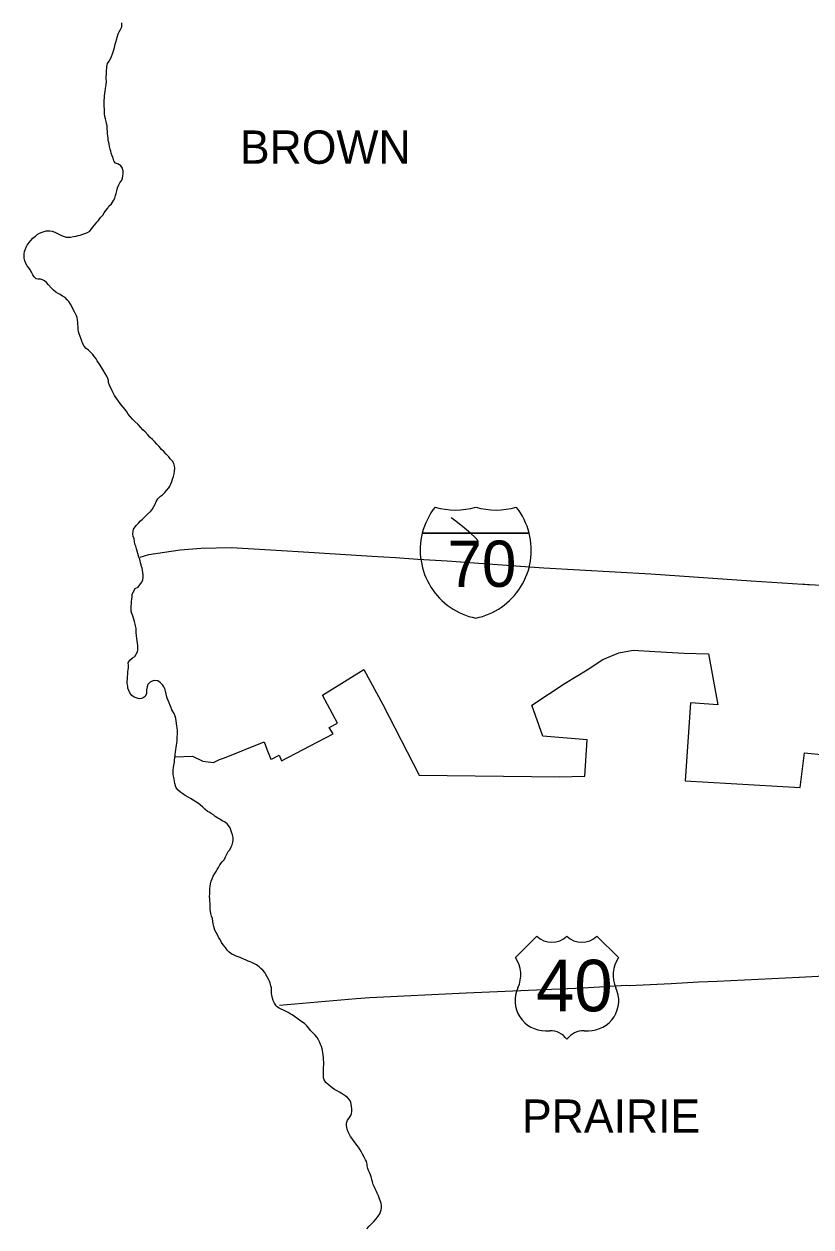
# Model space of a CAD drawing. Extents: x -1146 to -445, y -1283 to -822.
# Drawn here: x -1066.7 to -1013.6, y -1085.1 to -1003.9 of the extents above; entities that cross this region are included whole.
import ezdxf

# ---------------------------------------------------------------- set-up
doc = ezdxf.new("R2010")
doc.units = 0
for name, color, linetype in [('GM_X_County', 7, 'Continuous'), ('GM_X_County_Road', 7, 'Continuous'), ('GM_X_Interstate_Route', 7, 'Continuous'), ('GM_X_Interstate_Shield', 7, 'Continuous'), ('GM_X_Township', 7, 'Continuous'), ('GM_X_Township_Text', 7, 'Continuous'), ('GM_X_US_Route', 7, 'Continuous'), ('GM_X_US_Shield', 7, 'Continuous')]:
    doc.layers.add(name, color=color, linetype=linetype)

msp = doc.modelspace()

# ---------------------------------------------------------------- linework, layer by layer
at = {"layer": 'GM_X_County'}
msp.add_lwpolyline([(-1043.557, -1085.277), (-1043.4, -1085.092), (-1043.259, -1084.932), (-1043.097, -1084.782), (-1042.935, -1084.602), (-1042.793, -1084.422), (-1042.686, -1084.262), (-1042.64, -1084.137), (-1042.599, -1083.996), (-1042.583, -1083.826), (-1042.572, -1083.695), (-1042.592, -1083.564), (-1042.636, -1083.429), (-1042.72, -1083.257), (-1042.784, -1083.051), (-1042.869, -1082.875), (-1042.908, -1082.749), (-1042.993, -1082.583), (-1043.067, -1082.422), (-1043.137, -1082.281), (-1043.191, -1082.095), (-1043.225, -1081.944), (-1043.274, -1081.773), (-1043.329, -1081.637), (-1043.383, -1081.481), (-1043.452, -1081.325), (-1043.492, -1081.2), (-1043.541, -1081.029), (-1043.55, -1080.903), (-1043.595, -1080.737), (-1043.664, -1080.606), (-1043.754, -1080.435), (-1043.863, -1080.234), (-1043.932, -1080.098), (-1044.007, -1079.947), (-1044.137, -1079.765), (-1044.231, -1079.624), (-1044.331, -1079.498), (-1044.486, -1079.292), (-1044.58, -1079.16), (-1044.665, -1079.029), (-1044.745, -1078.904), (-1044.829, -1078.727), (-1044.893, -1078.551), (-1044.922, -1078.416), (-1044.942, -1078.29), (-1044.931, -1078.134), (-1044.864, -1077.944), (-1044.773, -1077.814), (-1044.656, -1077.613), (-1044.605, -1077.483), (-1044.584, -1077.357), (-1044.573, -1077.167), (-1044.592, -1077.016), (-1044.621, -1076.865), (-1044.656, -1076.739), (-1044.725, -1076.578), (-1044.875, -1076.412), (-1045.035, -1076.301), (-1045.295, -1076.119), (-1045.421, -1076.053), (-1045.581, -1075.967), (-1045.746, -1075.865), (-1045.916, -1075.749), (-1046.051, -1075.643), (-1046.177, -1075.537), (-1046.331, -1075.385), (-1046.446, -1075.219), (-1046.485, -1075.068), (-1046.504, -1074.912), (-1046.503, -1074.747), (-1046.497, -1074.581), (-1046.486, -1074.375), (-1046.48, -1074.194), (-1046.474, -1074.019), (-1046.483, -1073.848), (-1046.497, -1073.717), (-1046.511, -1073.531), (-1046.53, -1073.371), (-1046.589, -1073.109), (-1046.638, -1072.953), (-1046.688, -1072.817), (-1046.772, -1072.641), (-1046.831, -1072.515), (-1046.931, -1072.349), (-1047.061, -1072.203), (-1047.191, -1072.052), (-1047.36, -1071.885), (-1047.485, -1071.714), (-1047.62, -1071.563), (-1047.78, -1071.416), (-1047.945, -1071.3), (-1048.11, -1071.189), (-1048.29, -1071.057), (-1048.606, -1070.83), (-1048.736, -1070.759), (-1048.886, -1070.663), (-1049.057, -1070.571), (-1049.192, -1070.505), (-1049.362, -1070.439), (-1049.488, -1070.383), (-1049.663, -1070.257), (-1049.721, -1070.168), (-1049.802, -1070.041), (-1049.887, -1069.864), (-1049.941, -1069.693), (-1049.985, -1069.497), (-1049.999, -1069.367), (-1050.003, -1069.206), (-1050.012, -1069.005), (-1050.042, -1068.874), (-1050.096, -1068.693), (-1050.145, -1068.548), (-1050.21, -1068.422), (-1050.299, -1068.261), (-1050.394, -1068.095), (-1050.458, -1067.969), (-1050.588, -1067.802), (-1050.718, -1067.701), (-1050.848, -1067.59), (-1051.023, -1067.459), (-1051.199, -1067.363), (-1051.324, -1067.297), (-1051.449, -1067.236), (-1051.575, -1067.19), (-1051.705, -1067.129), (-1051.871, -1067.073), (-1051.996, -1067.022), (-1052.126, -1066.962), (-1052.262, -1066.911), (-1052.397, -1066.855), (-1052.522, -1066.799), (-1052.683, -1066.733), (-1052.858, -1066.597), (-1053.003, -1066.45), (-1053.118, -1066.284), (-1053.267, -1066.108), (-1053.392, -1065.931), (-1053.481, -1065.745), (-1053.556, -1065.614), (-1053.63, -1065.468), (-1053.75, -1065.272), (-1053.834, -1065.106), (-1053.898, -1064.865), (-1053.937, -1064.689), (-1053.961, -1064.513), (-1053.995, -1064.327), (-1054.05, -1064.156), (-1054.099, -1063.985), (-1054.128, -1063.829), (-1054.143, -1063.704), (-1054.151, -1063.433), (-1054.155, -1063.292), (-1054.159, -1063.156), (-1054.173, -1062.991), (-1054.183, -1062.835), (-1054.176, -1062.664), (-1054.175, -1062.499), (-1054.164, -1062.313), (-1054.153, -1062.132), (-1054.127, -1061.987), (-1054.071, -1061.807), (-1054.019, -1061.631), (-1053.933, -1061.461), (-1053.831, -1061.281), (-1053.745, -1061.146), (-1053.674, -1061.015), (-1053.588, -1060.875), (-1053.486, -1060.695), (-1053.334, -1060.5), (-1053.207, -1060.35), (-1053.121, -1060.15), (-1053.024, -1059.979), (-1052.928, -1059.804), (-1052.826, -1059.674), (-1052.73, -1059.484), (-1052.663, -1059.334), (-1052.607, -1059.158), (-1052.596, -1059.003), (-1052.6, -1058.847), (-1052.634, -1058.666), (-1052.699, -1058.495), (-1052.748, -1058.334), (-1052.801, -1058.189), (-1052.904, -1058.042), (-1053.007, -1057.922), (-1053.182, -1057.795), (-1053.327, -1057.719), (-1053.498, -1057.613), (-1053.623, -1057.537), (-1053.798, -1057.421), (-1053.923, -1057.33), (-1054.074, -1057.239), (-1054.204, -1057.148), (-1054.329, -1057.087), (-1054.514, -1056.931), (-1054.644, -1056.804), (-1054.814, -1056.648), (-1054.944, -1056.552), (-1055.109, -1056.431), (-1055.285, -1056.329), (-1055.465, -1056.223), (-1055.63, -1056.122), (-1055.841, -1056.006), (-1055.996, -1055.899), (-1056.121, -1055.819), (-1056.301, -1055.657), (-1056.431, -1055.491), (-1056.49, -1055.36), (-1056.525, -1055.209), (-1056.554, -1055.059), (-1056.588, -1054.878), (-1056.622, -1054.712), (-1056.642, -1054.571), (-1056.646, -1054.436), (-1056.64, -1054.295), (-1056.619, -1054.115), (-1056.593, -1053.969), (-1056.561, -1053.774), (-1056.545, -1053.613), (-1056.535, -1053.483), (-1056.523, -1053.392), (-1056.519, -1053.357), (-1056.503, -1053.212), (-1056.482, -1053.081), (-1056.461, -1052.916), (-1056.44, -1052.765), (-1056.424, -1052.615), (-1056.403, -1052.469), (-1056.382, -1052.294), (-1056.376, -1052.153), (-1056.365, -1052.023), (-1056.359, -1051.892), (-1056.353, -1051.762), (-1056.358, -1051.616), (-1056.372, -1051.456), (-1056.391, -1051.31), (-1056.439, -1050.979), (-1056.468, -1050.813), (-1056.503, -1050.662), (-1056.587, -1050.486), (-1056.662, -1050.35), (-1056.726, -1050.219), (-1056.786, -1050.094), (-1056.855, -1049.928), (-1056.915, -1049.767), (-1056.989, -1049.596), (-1057.048, -1049.45), (-1057.093, -1049.279), (-1057.117, -1049.153), (-1057.161, -1048.993), (-1057.196, -1048.867), (-1057.28, -1048.686), (-1057.35, -1048.56), (-1057.515, -1048.379), (-1057.67, -1048.267), (-1057.931, -1048.246), (-1058.062, -1048.286), (-1058.188, -1048.355), (-1058.345, -1048.53), (-1058.411, -1048.685), (-1058.438, -1048.871), (-1058.438, -1049.002), (-1058.439, -1049.132), (-1058.532, -1049.324), (-1058.667, -1049.427), (-1058.793, -1049.459), (-1058.942, -1049.485), (-1059.282, -1049.366), (-1059.441, -1049.253), (-1059.564, -1049.091), (-1059.641, -1048.929), (-1059.699, -1048.772), (-1059.717, -1048.632), (-1059.744, -1048.456), (-1059.742, -1048.32), (-1059.734, -1048.15), (-1059.722, -1047.979), (-1059.709, -1047.849), (-1059.697, -1047.683), (-1059.679, -1047.508), (-1059.662, -1047.383), (-1059.654, -1047.227), (-1059.677, -1047.056), (-1059.579, -1046.877), (-1059.401, -1046.724), (-1059.233, -1046.617), (-1059.051, -1046.318), (-1059.025, -1046.183), (-1059.024, -1046.048), (-1059.028, -1045.877), (-1059.042, -1045.741), (-1059.076, -1045.55), (-1059.101, -1045.385), (-1059.115, -1045.244), (-1059.133, -1044.993), (-1059.138, -1044.868), (-1059.152, -1044.732), (-1059.181, -1044.566), (-1059.211, -1044.441), (-1059.265, -1044.27), (-1059.36, -1043.885), (-1059.433, -1043.718), (-1059.481, -1043.557), (-1059.488, -1043.391), (-1059.485, -1043.225), (-1059.468, -1043.055), (-1059.45, -1042.89), (-1059.433, -1042.764), (-1059.42, -1042.604), (-1059.403, -1042.439), (-1059.355, -1042.274), (-1059.208, -1042.034), (-1059.016, -1041.945), (-1058.895, -1041.785), (-1058.774, -1041.634), (-1058.704, -1041.473), (-1058.679, -1041.298), (-1058.679, -1041.122), (-1058.704, -1040.947), (-1058.724, -1040.801), (-1058.749, -1040.661), (-1058.804, -1040.49), (-1058.812, -1040.436), (-1058.849, -1040.305), (-1058.88, -1040.16), (-1058.925, -1040.019), (-1058.954, -1039.918), (-1059.025, -1039.668), (-1059.086, -1039.518), (-1059.121, -1039.352), (-1059.176, -1039.187), (-1059.231, -1039.036), (-1059.283, -1038.682), (-1059.345, -1038.52), (-1059.363, -1038.344), (-1059.355, -1038.164), (-1059.313, -1038.029), (-1059.146, -1037.776), (-1058.994, -1037.616), (-1058.847, -1037.466), (-1058.711, -1037.351), (-1058.534, -1037.181), (-1058.382, -1037.027), (-1058.18, -1036.847), (-1058.074, -1036.697), (-1057.952, -1036.507), (-1057.86, -1036.336), (-1057.794, -1036.171), (-1057.672, -1035.981), (-1057.495, -1035.801), (-1057.369, -1035.701), (-1057.207, -1035.547), (-1057.086, -1035.417), (-1056.934, -1035.247), (-1056.863, -1035.117), (-1056.797, -1034.986), (-1056.73, -1034.821), (-1056.679, -1034.661), (-1056.623, -1034.465), (-1056.586, -1034.295), (-1056.555, -1034.119), (-1056.539, -1033.904), (-1056.553, -1033.773), (-1056.592, -1033.607), (-1056.682, -1033.436), (-1056.837, -1033.28), (-1056.941, -1033.144), (-1057.111, -1032.967), (-1057.271, -1032.791), (-1057.426, -1032.64), (-1057.591, -1032.443), (-1057.741, -1032.292), (-1057.916, -1032.11), (-1058.045, -1031.969), (-1058.19, -1031.833), (-1058.365, -1031.651), (-1058.535, -1031.465), (-1058.695, -1031.319), (-1058.855, -1031.152), (-1059.015, -1030.961), (-1059.237, -1030.763), (-1059.4, -1030.61), (-1059.543, -1030.432), (-1059.676, -1030.265), (-1059.769, -1030.113), (-1059.887, -1029.95), (-1060.019, -1029.783), (-1060.147, -1029.634), (-1060.346, -1029.382), (-1060.615, -1028.993), (-1060.759, -1028.688), (-1060.95, -1028.305), (-1061.003, -1028.132), (-1061.02, -1027.983), (-1061.053, -1027.859), (-1061.123, -1027.689), (-1061.227, -1027.52), (-1061.4, -1027.259), (-1061.582, -1026.945), (-1061.781, -1026.66), (-1061.855, -1026.532), (-1061.947, -1026.401), (-1062.07, -1026.228), (-1062.218, -1026.071), (-1062.356, -1025.933), (-1062.521, -1025.835), (-1062.658, -1025.672), (-1062.736, -1025.526), (-1062.804, -1025.344), (-1062.862, -1025.208), (-1062.924, -1025.016), (-1062.987, -1024.849), (-1063.029, -1024.698), (-1063.057, -1024.527), (-1063.064, -1024.346), (-1063.072, -1024.216), (-1063.084, -1024.06), (-1063.102, -1023.914), (-1063.135, -1023.748), (-1063.173, -1023.617), (-1063.231, -1023.486), (-1063.299, -1023.354), (-1063.397, -1023.187), (-1063.494, -1023), (-1063.582, -1022.843), (-1063.699, -1022.665), (-1063.803, -1022.538), (-1063.946, -1022.391), (-1064.11, -1022.298), (-1064.284, -1022.18), (-1064.408, -1022.126), (-1064.577, -1022.019), (-1064.727, -1021.892), (-1064.89, -1021.725), (-1065.059, -1021.542), (-1065.208, -1021.375), (-1065.337, -1021.253), (-1065.467, -1021.192), (-1065.612, -1021.155), (-1065.752, -1021.139), (-1065.888, -1021.117), (-1066.027, -1020.985), (-1066.111, -1020.859), (-1066.19, -1020.723), (-1066.308, -1020.526), (-1066.401, -1020.374), (-1066.495, -1020.248), (-1066.604, -1020.081), (-1066.672, -1019.909), (-1066.711, -1019.728), (-1066.714, -1019.593), (-1066.708, -1019.462), (-1066.68, -1019.287), (-1066.634, -1019.157), (-1066.567, -1018.987), (-1066.495, -1018.857), (-1066.372, -1018.673), (-1066.265, -1018.534), (-1066.128, -1018.375), (-1065.951, -1018.241), (-1065.819, -1018.137), (-1065.682, -1018.048), (-1065.496, -1017.971), (-1065.364, -1017.926), (-1065.228, -1017.882), (-1065.093, -1017.874), (-1064.967, -1017.875), (-1064.807, -1017.912), (-1064.627, -1017.974), (-1064.462, -1018.056), (-1064.238, -1018.184), (-1064.063, -1018.256), (-1063.873, -1018.308), (-1063.712, -1018.32), (-1063.571, -1018.306), (-1063.37, -1018.268), (-1063.204, -1018.235), (-1063.063, -1018.206), (-1062.927, -1018.177), (-1062.751, -1018.114), (-1062.614, -1018.065), (-1062.438, -1018.007), (-1062.281, -1017.898), (-1062.088, -1017.659), (-1061.945, -1017.48), (-1061.807, -1017.306), (-1061.681, -1017.182), (-1061.543, -1016.993), (-1061.4, -1016.818), (-1061.303, -1016.679), (-1061.181, -1016.52), (-1061.064, -1016.355), (-1060.982, -1016.226), (-1060.814, -1016.052), (-1060.671, -1015.838), (-1060.594, -1015.673), (-1060.532, -1015.503), (-1060.505, -1015.363), (-1060.458, -1015.187), (-1060.395, -1014.992), (-1060.308, -1014.772), (-1060.241, -1014.643), (-1060.118, -1014.453), (-1060.066, -1014.323), (-1060.035, -1014.178), (-1060.023, -1014.038), (-1060.031, -1013.857), (-1060.069, -1013.661), (-1060.172, -1013.489), (-1060.332, -1013.392), (-1060.537, -1013.305), (-1060.619, -1013.202), (-1060.651, -1013.163), (-1060.699, -1012.987), (-1060.757, -1012.816), (-1060.831, -1012.634), (-1060.864, -1012.503), (-1060.893, -1012.378), (-1060.936, -1012.201), (-1060.969, -1012.02), (-1061.003, -1011.86), (-1061.026, -1011.734), (-1061.045, -1011.608), (-1061.064, -1011.482), (-1061.077, -1011.312), (-1061.085, -1011.176), (-1061.098, -1010.975), (-1061.111, -1010.794), (-1061.139, -1010.629), (-1061.178, -1010.503), (-1061.216, -1010.327), (-1061.249, -1010.156), (-1061.272, -1009.955), (-1061.281, -1009.829), (-1061.289, -1009.643), (-1061.297, -1009.498), (-1061.305, -1009.337), (-1061.309, -1009.197), (-1061.302, -1009.061), (-1061.285, -1008.906), (-1061.274, -1008.775), (-1061.262, -1008.62), (-1061.24, -1008.455), (-1061.213, -1008.269), (-1061.191, -1008.129), (-1061.175, -1007.994), (-1061.157, -1007.803), (-1061.16, -1007.627), (-1061.159, -1007.462), (-1061.147, -1007.311), (-1061.145, -1007.186), (-1061.139, -1007.06), (-1061.132, -1006.925), (-1061.126, -1006.79), (-1061.073, -1006.594), (-1060.966, -1006.435), (-1060.869, -1006.27), (-1060.802, -1006.106), (-1060.735, -1005.936), (-1060.698, -1005.795), (-1060.656, -1005.67), (-1060.614, -1005.495), (-1060.562, -1005.285), (-1060.52, -1005.145), (-1060.457, -1004.925), (-1060.425, -1004.8), (-1060.348, -1004.59), (-1060.281, -1004.455), (-1060.204, -1004.295), (-1060.121, -1004.105), (-1060.1, -1003.98), (-1060.103, -1003.85)], dxfattribs=at)
at = {"layer": 'GM_X_County_Road'}
msp.add_lwpolyline([(-1036.078, -1038.806), (-1036.259, -1038.603), (-1036.575, -1038.291), (-1036.971, -1037.953), (-1037.555, -1037.491), (-1037.868, -1037.259)], dxfattribs=at)
at = {"layer": 'GM_X_Interstate_Route'}
for points in [[(-1058.884, -1039.923), (-1058.298, -1039.748), (-1056.182, -1039.425), (-1054.749, -1039.308), (-1052.71, -1039.265), (-1048.954, -1039.487), (-1048.195, -1039.544), (-1043.201, -1039.862), (-1041.632, -1039.933), (-1040.125, -1040.056), (-1038.138, -1040.169), (-1036.001, -1040.335), (-1031.615, -1040.646), (-1024.384, -1041.041), (-1017.611, -1041.528), (-1014.121, -1041.746), (-1013.99, -1041.755), (-1013.798, -1041.766)], [(-1013.798, -1041.766), (-1013.666, -1041.775)], [(-1013.666, -1041.775), (-1012.91, -1041.822), (-1012.206, -1041.866)]]:
    msp.add_lwpolyline(points, dxfattribs=at)
at = {"layer": 'GM_X_Interstate_Shield'}
for p, q in [((-1039.819, -1038.293), (-1032.605, -1038.293)), ((-1032.605, -1038.293), (-1039.819, -1038.293)), ((-1032.605, -1038.293), (-1039.819, -1038.293))]:
    msp.add_line(p, q, dxfattribs=at)
for centre, start, end in [((-1035.274, -1039.442), 141.66896, 165.80665), ((-1037.582, -1032.052), 253.00908, 286.99093), ((-1034.842, -1032.052), 253.00908, 286.99093), ((-1037.149, -1039.442), 14.19335, 38.33104), ((-1035.274, -1039.442), 165.80665, 258.46304), ((-1037.149, -1039.442), 281.53696, 14.19335)]:
    msp.add_arc(centre, 4.688, start, end, dxfattribs=at)
at = {"layer": 'GM_X_Township'}
msp.add_lwpolyline([(-1056.523, -1053.392), (-1055.339, -1053.356), (-1054.65, -1053.69), (-1053.929, -1053.794), (-1053.521, -1053.575), (-1053.176, -1053.48), (-1050.504, -1052.393), (-1050.316, -1052.88), (-1050.054, -1053.565), (-1049.969, -1053.53), (-1049.489, -1053.297), (-1049.338, -1053.669), (-1047.387, -1052.67), (-1045.845, -1051.849), (-1046.106, -1051.42), (-1045.541, -1051.138), (-1046.556, -1049.234), (-1043.763, -1047.509), (-1042.494, -1049.875), (-1040.035, -1054.641), (-1030.565, -1054.743), (-1028.845, -1054.704), (-1028.698, -1052.257), (-1031.689, -1052.016), (-1032.432, -1049.904), (-1030.162, -1048.44), (-1028.688, -1047.519), (-1027.621, -1046.829), (-1026.554, -1046.39), (-1025.592, -1046.201), (-1024.107, -1046.285), (-1022.141, -1046.411), (-1020.489, -1046.452), (-1019.861, -1049.883), (-1021.702, -1049.757), (-1022.078, -1055.028), (-1014.3, -1055.479), (-1014.013, -1053.141), (-1009.102, -1053.617)], dxfattribs=at)
at = {"layer": 'GM_X_US_Route'}
for points in [[(-1043.371, -1069.665), (-1036.862, -1069.334), (-1028.965, -1068.995), (-1026.028, -1068.832), (-1025.848, -1068.833), (-1023.012, -1068.7), (-1021.174, -1068.604), (-1019.911, -1068.543), (-1014.37, -1068.275), (-1009.235, -1068.021)], [(-1049.464, -1070.163), (-1044.283, -1069.711), (-1043.371, -1069.665)]]:
    msp.add_lwpolyline(points, dxfattribs=at)
at = {"layer": 'GM_X_US_Shield'}
for p, q in [((-1032.086, -1065.514), (-1033.536, -1066.964)), ((-1026.575, -1066.964), (-1028.025, -1065.514)), ((-1031.506, -1071.895), (-1031.216, -1071.895)), ((-1028.895, -1071.895), (-1028.605, -1071.895))]:
    msp.add_line(p, q, dxfattribs=at)
for centre, radius, start, end in [((-1031.071, -1064.478), 1.45, 225.573, 314.427), ((-1029.04, -1064.478), 1.45, 225.573, 314.427), ((-1035.199, -1068.128), 2.03, 334.54712, 35.00093), ((-1024.912, -1068.128), 2.03, 144.99907, 205.45288), ((-1031.528, -1069.864), 2.03, 154.83192, 270.63826), ((-1028.583, -1069.864), 2.03, 269.36174, 25.16808), ((-1031.216, -1073.345), 1.45, 36.8699, 90), ((-1028.895, -1073.345), 1.45, 90, 143.1301)]:
    msp.add_arc(centre, radius, start, end, dxfattribs=at)

# ---------------------------------------------------------------- texts
at = {"layer": 'GM_X_Interstate_Shield'}
msp.add_text('70', height=3.125, dxfattribs=at).set_placement((-1038.118, -1041.926))
at = {"layer": 'GM_X_Township_Text'}
for s, p in [('BROWN', (-1052.14, -1013.358)), ('PRAIRIE', (-1033.091, -1078.791))]:
    msp.add_text(s, height=2.25, rotation=0.00001, dxfattribs=at).set_placement(p)
at = {"layer": 'GM_X_US_Shield'}
msp.add_text('40', height=3.4805, dxfattribs=at).set_placement((-1032.146, -1070.589))

doc.saveas('drawing.dxf')
